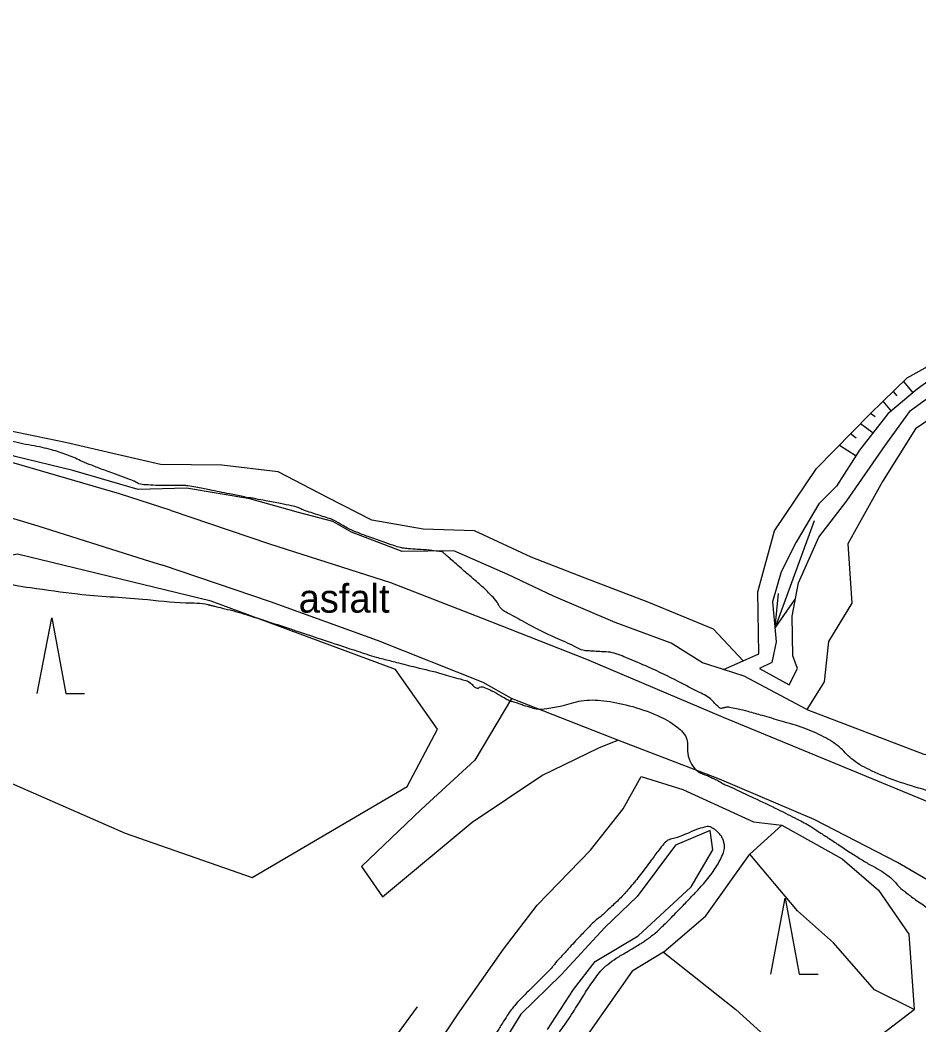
# Model space of a CAD drawing. Extents: x -475575 to -473225, y -1116053 to -1114104.
# Drawn here: x -473889.9 to -473842.5, y -1115632.7 to -1115579.7 of the extents above; entities that cross this region are included whole.
import ezdxf

# ---------------------------------------------------------------- set-up
doc = ezdxf.new("R2010")
doc.units = 0
doc.layers.add('Vrstevnice_vedlejsi', color=7, linetype='Continuous')
doc.layers.add('Vrstva_10', color=7, linetype='Continuous')

msp = doc.modelspace()

# ---------------------------------------------------------------- linework, layer by layer
at = {"layer": 'Vrstevnice_vedlejsi'}
for points in [[(-473898.863, -1115590.941), (-473898.35500000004, -1115588.119), (-473897.685, -1115585.314), (-473896.85400000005, -1115582.527), (-473895.863, -1115579.757), (-473895.07, -1115577.408), (-473894.47500000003, -1115575.479), (-473894.07800000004, -1115573.969), (-473893.923, -1115572.8050000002), (-473894.009, -1115571.985), (-473894.336, -1115571.51), (-473894.411, -1115569.968), (-473894.233, -1115567.357), (-473893.80100000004, -1115563.679), (-473892.655, -1115560.5990000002), (-473890.79500000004, -1115558.118), (-473888.22000000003, -1115556.237), (-473885.87600000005, -1115554.48), (-473883.76300000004, -1115552.85), (-473881.88200000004, -1115551.344), (-473877.041, -1115547.641), (-473869.242, -1115541.74), (-473858.483, -1115533.641), (-473850.92500000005, -1115528.022), (-473846.565, -1115524.882), (-473845.405, -1115524.2210000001), (-473843.21300000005, -1115523.172), (-473839.989, -1115521.735), (-473835.732, -1115519.909), (-473830.05100000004, -1115523.3490000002), (-473822.946, -1115532.0550000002), (-473814.417, -1115546.0280000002), (-473808.341, -1115555.6060000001), (-473804.71800000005, -1115560.789), (-473803.549, -1115561.578), (-473802.722, -1115562.1670000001), (-473802.237, -1115562.5550000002), (-473802.09300000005, -1115562.742), (-473802.14, -1115563.413), (-473802.379, -1115564.5690000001), (-473802.808, -1115566.21), (-473802.66500000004, -1115567.262), (-473801.95, -1115567.726), (-473800.662, -1115567.601), (-473799.61100000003, -1115567.898), (-473798.79500000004, -1115568.615), (-473798.21400000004, -1115569.753), (-473797.28400000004, -1115570.6700000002), (-473796.004, -1115571.365), (-473794.373, -1115571.8390000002), (-473792.50700000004, -1115572.905), (-473790.40400000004, -1115574.566), (-473788.06600000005, -1115576.82), (-473786.25200000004, -1115578.34), (-473784.96300000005, -1115579.1260000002), (-473784.199, -1115579.1770000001), (-473783.66500000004, -1115579.272), (-473783.36100000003, -1115579.408), (-473783.287, -1115579.587), (-473783.168, -1115579.7510000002), (-473783.00200000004, -1115579.9000000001), (-473782.791, -1115580.0350000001), (-473782.597, -1115580.119), (-473782.42100000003, -1115580.151), (-473782.26300000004, -1115580.1330000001), (-473782.069, -1115580.075), (-473781.83900000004, -1115579.9780000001), (-473781.574, -1115579.841), (-473781.348, -1115579.73), (-473781.161, -1115579.645), (-473781.015, -1115579.585), (-473780.88, -1115579.534), (-473780.755, -1115579.4910000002), (-473780.64200000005, -1115579.4570000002), (-473780.40900000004, -1115579.301), (-473780.058, -1115579.024), (-473779.587, -1115578.6260000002), (-473779.184, -1115578.3260000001), (-473778.847, -1115578.125), (-473778.57800000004, -1115578.022), (-473778.23600000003, -1115577.896), (-473777.819, -1115577.745), (-473777.329, -1115577.571), (-473776.63200000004, -1115577.3800000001), (-473775.728, -1115577.172), (-473774.617, -1115576.948), (-473773.862, -1115576.801), (-473773.465, -1115576.732), (-473773.424, -1115576.7410000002), (-473773.38200000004, -1115576.7510000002), (-473773.33800000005, -1115576.762), (-473773.294, -1115576.773), (-473772.905, -1115577.046), (-473772.17100000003, -1115577.5790000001), (-473771.09400000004, -1115578.374), (-473770.33900000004, -1115578.918), (-473769.906, -1115579.213)], [(-473855.174, -1115614.605), (-473856.74100000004, -1115613.852), (-473857.939, -1115613.34), (-473858.76900000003, -1115613.067), (-473859.23000000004, -1115613.0350000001), (-473859.60000000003, -1115613.011), (-473859.879, -1115612.997), (-473860.06600000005, -1115612.992), (-473860.656, -1115612.76), (-473861.65, -1115612.3020000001), (-473863.047, -1115611.617), (-473864.026, -1115611.075), (-473864.58900000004, -1115610.6770000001), (-473864.734, -1115610.421), (-473865.025, -1115610.081), (-473865.46300000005, -1115609.655), (-473866.048, -1115609.1430000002), (-473866.527, -1115608.7240000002), (-473866.902, -1115608.398), (-473867.172, -1115608.164), (-473867.375, -1115607.986), (-473867.511, -1115607.862), (-473867.579, -1115607.794), (-473867.842, -1115607.733), (-473868.299, -1115607.6800000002), (-473868.95, -1115607.635), (-473869.42500000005, -1115607.597), (-473869.723, -1115607.567), (-473869.84400000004, -1115607.543), (-473870.189, -1115607.435), (-473870.756, -1115607.24), (-473871.547, -1115606.9610000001), (-473872.174, -1115606.717), (-473872.64, -1115606.5080000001), (-473872.94200000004, -1115606.335), (-473873.16500000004, -1115606.208), (-473873.309, -1115606.1260000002), (-473873.373, -1115606.09), (-473873.586, -1115606.012), (-473873.94800000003, -1115605.891), (-473874.45800000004, -1115605.727), (-473874.84400000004, -1115605.5960000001), (-473875.10500000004, -1115605.497), (-473875.243, -1115605.4300000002), (-473875.59500000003, -1115605.3360000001), (-473876.162, -1115605.215), (-473876.945, -1115605.067), (-473877.478, -1115604.968), (-473877.76200000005, -1115604.9170000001), (-473877.797, -1115604.916), (-473878.167, -1115604.845), (-473878.87, -1115604.7040000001), (-473879.908, -1115604.494), (-473880.63800000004, -1115604.351), (-473881.059, -1115604.276), (-473881.172, -1115604.269), (-473881.492, -1115604.263), (-473882.02, -1115604.2580000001), (-473882.756, -1115604.2550000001), (-473883.299, -1115604.2240000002), (-473883.64900000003, -1115604.168), (-473883.80600000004, -1115604.085), (-473884.168, -1115603.936), (-473884.734, -1115603.7210000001), (-473885.504, -1115603.44), (-473886.13700000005, -1115603.1970000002), (-473886.631, -1115602.993), (-473886.988, -1115602.827), (-473887.36000000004, -1115602.675), (-473887.74600000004, -1115602.5350000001), (-473888.147, -1115602.409), (-473888.62, -1115602.289), (-473889.166, -1115602.174), (-473889.783, -1115602.065), (-473890.364, -1115601.922), (-473890.907, -1115601.747), (-473891.413, -1115601.538), (-473892.02, -1115601.304), (-473892.727, -1115601.0450000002), (-473893.536, -1115600.761), (-473894.18200000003, -1115600.5180000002), (-473894.667, -1115600.315), (-473894.99100000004, -1115600.151), (-473895.5, -1115599.8900000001), (-473896.194, -1115599.53), (-473897.075, -1115599.073), (-473897.715, -1115598.744), (-473898.114, -1115598.5450000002), (-473898.27300000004, -1115598.475), (-473898.558, -1115598.313), (-473898.96900000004, -1115598.058), (-473899.506, -1115597.71), (-473899.78900000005, -1115597.0790000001), (-473899.819, -1115596.163), (-473899.59500000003, -1115594.963), (-473899.277, -1115593.223), (-473898.863, -1115590.941)], [(-473918.52735009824, -1115615.8243041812), (-473918.527, -1115615.824), (-473916.922, -1115614.645), (-473915.13200000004, -1115613.726), (-473912.96900000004, -1115612.688), (-473910.433, -1115611.531), (-473907.525, -1115610.2550000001), (-473905.55600000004, -1115609.378), (-473904.526, -1115608.902), (-473904.435, -1115608.825), (-473904.368, -1115608.7680000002), (-473904.324, -1115608.729), (-473904.30500000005, -1115608.709), (-473903.532, -1115608.5080000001), (-473902.00700000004, -1115608.127), (-473899.72900000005, -1115607.566), (-473897.987, -1115607.267), (-473896.781, -1115607.2310000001), (-473896.112, -1115607.458), (-473895.516, -1115607.621), (-473894.992, -1115607.7210000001), (-473894.542, -1115607.756), (-473894.043, -1115607.842), (-473893.494, -1115607.9780000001), (-473892.897, -1115608.165), (-473892.27400000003, -1115608.441), (-473891.62600000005, -1115608.8050000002), (-473890.95300000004, -1115609.2580000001), (-473889.367, -1115609.652), (-473886.869, -1115609.986), (-473883.45900000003, -1115610.261), (-473881.17100000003, -1115610.448), (-473880.003, -1115610.547), (-473879.957, -1115610.5590000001), (-473879.91400000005, -1115610.57), (-473879.875, -1115610.58), (-473879.83800000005, -1115610.5890000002), (-473879.628, -1115610.639), (-473879.243, -1115610.733), (-473878.683, -1115610.868), (-473877.574, -1115611.205), (-473875.91400000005, -1115611.743), (-473873.70300000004, -1115612.483), (-473872.107, -1115613.009), (-473871.124, -1115613.321), (-473870.756, -1115613.419), (-473870.05500000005, -1115613.597), (-473869.021, -1115613.8560000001), (-473867.655, -1115614.196), (-473866.693, -1115614.476), (-473866.135, -1115614.696), (-473865.981, -1115614.8560000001), (-473865.841, -1115614.942), (-473865.716, -1115614.952)], [(-473787.44200000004, -1115614.95), (-473789.08300000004, -1115614.87), (-473790.19100000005, -1115614.817), (-473790.764, -1115614.7920000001), (-473790.802, -1115614.7950000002), (-473790.829, -1115614.797), (-473790.84300000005, -1115614.799), (-473790.846, -1115614.8020000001), (-473791.14200000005, -1115614.941), (-473791.734, -1115615.218), (-473792.619, -1115615.632), (-473793.44200000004, -1115615.992), (-473794.201, -1115616.298), (-473794.896, -1115616.55), (-473795.445, -1115616.8090000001), (-473795.847, -1115617.073), (-473796.103, -1115617.344), (-473796.93200000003, -1115617.5080000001), (-473798.336, -1115617.566), (-473800.313, -1115617.517), (-473801.81700000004, -1115617.777), (-473802.84900000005, -1115618.3460000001), (-473803.40900000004, -1115619.2240000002), (-473804.043, -1115619.781), (-473804.75200000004, -1115620.017), (-473805.53500000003, -1115619.932), (-473806.19, -1115619.8900000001), (-473806.71800000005, -1115619.8930000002), (-473807.117, -1115619.939), (-473807.568, -1115619.9610000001), (-473808.07, -1115619.959), (-473808.62200000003, -1115619.932), (-473809.50100000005, -1115620.717), (-473810.704, -1115622.313), (-473812.233, -1115624.72), (-473813.36000000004, -1115626.299), (-473814.08300000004, -1115627.051), (-473814.40400000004, -1115626.975), (-473815.069, -1115626.8730000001), (-473816.07800000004, -1115626.746), (-473817.43100000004, -1115626.593), (-473818.49100000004, -1115626.466), (-473819.25800000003, -1115626.365), (-473819.732, -1115626.291), (-473820.472, -1115626.1500000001), (-473821.476, -1115625.942), (-473822.745, -1115625.668), (-473823.906, -1115625.423), (-473824.95800000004, -1115625.2070000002), (-473825.902, -1115625.021), (-473826.77900000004, -1115624.814), (-473827.59, -1115624.5860000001), (-473828.335, -1115624.338), (-473829.00700000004, -1115624.1500000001), (-473829.608, -1115624.021), (-473830.136, -1115623.9510000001), (-473830.772, -1115623.8490000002), (-473831.515, -1115623.7140000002), (-473832.36600000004, -1115623.5450000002), (-473833.048, -1115623.359), (-473833.56200000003, -1115623.154), (-473833.90900000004, -1115622.9300000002), (-473834.20800000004, -1115622.723), (-473834.461, -1115622.531), (-473834.667, -1115622.3560000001), (-473835.119, -1115622.146), (-473835.81600000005, -1115621.902), (-473836.759, -1115621.6230000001), (-473837.57300000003, -1115621.401), (-473838.25800000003, -1115621.235), (-473838.815, -1115621.1260000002), (-473839.335, -1115621.0280000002), (-473839.818, -1115620.942), (-473840.26300000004, -1115620.8660000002), (-473841.082, -1115620.6500000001), (-473842.27400000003, -1115620.294), (-473843.83900000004, -1115619.797), (-473845.09400000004, -1115619.26), (-473846.03900000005, -1115618.682), (-473846.674, -1115618.064), (-473847.504, -1115617.527), (-473848.52900000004, -1115617.071), (-473849.749, -1115616.6970000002), (-473850.73500000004, -1115616.405), (-473851.488, -1115616.196), (-473852.00800000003, -1115616.0690000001), (-473852.386, -1115615.992), (-473852.62200000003, -1115615.9640000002), (-473852.715, -1115615.985), (-473852.79600000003, -1115616.004), (-473852.86500000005, -1115616.02), (-473852.922, -1115616.034), (-473853.03, -1115615.967), (-473853.189, -1115615.818), (-473853.39800000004, -1115615.587), (-473854.06, -1115615.183), (-473855.174, -1115614.605)], [(-473865.716, -1115614.952), (-473865.60400000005, -1115614.888), (-473865.37100000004, -1115614.935), (-473865.015, -1115615.095), (-473864.537, -1115615.3660000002), (-473864.20300000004, -1115615.55), (-473864.01200000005, -1115615.645), (-473863.965, -1115615.652), (-473863.87100000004, -1115615.679), (-473863.73000000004, -1115615.725), (-473863.542, -1115615.791), (-473863.303, -1115615.868), (-473863.014, -1115615.955), (-473862.67600000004, -1115616.0520000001), (-473862.109, -1115616.03), (-473861.315, -1115615.888), (-473860.294, -1115615.6260000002), (-473859.112, -1115615.625), (-473857.77, -1115615.884), (-473856.26800000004, -1115616.404), (-473855.25100000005, -1115616.996), (-473854.71900000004, -1115617.661), (-473854.672, -1115618.399), (-473854.476, -1115618.9640000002), (-473854.131, -1115619.3560000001), (-473853.63700000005, -1115619.5760000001), (-473853.26900000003, -1115619.7480000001), (-473853.025, -1115619.871), (-473852.907, -1115619.946), (-473852.79600000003, -1115620.0080000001), (-473852.69200000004, -1115620.057), (-473852.596, -1115620.092), (-473852.098, -1115620.3220000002), (-473851.19800000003, -1115620.749), (-473849.896, -1115621.37), (-473848.89, -1115621.8760000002), (-473848.179, -1115622.264), (-473847.764, -1115622.536), (-473847.28, -1115622.854), (-473846.728, -1115623.217), (-473846.108, -1115623.627), (-473845.536, -1115623.9880000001), (-473845.011, -1115624.299), (-473844.53500000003, -1115624.5620000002), (-473844.141, -1115624.825), (-473843.83, -1115625.09), (-473843.602, -1115625.3560000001), (-473843.23500000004, -1115625.682), (-473842.728, -1115626.0690000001), (-473842.08300000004, -1115626.5150000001), (-473841.466, -1115627.0010000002), (-473840.87700000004, -1115627.526), (-473840.31600000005, -1115628.092), (-473839.84900000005, -1115628.541), (-473839.47500000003, -1115628.875), (-473839.194, -1115629.094), (-473838.93700000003, -1115629.283), (-473838.704, -1115629.4440000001), (-473838.495, -1115629.574), (-473838.13200000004, -1115629.887), (-473837.61600000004, -1115630.381), (-473836.946, -1115631.057), (-473836.35400000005, -1115631.7550000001), (-473835.84, -1115632.475), (-473835.40300000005, -1115633.217), (-473835.03900000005, -1115633.7580000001), (-473834.748, -1115634.1), (-473834.52900000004, -1115634.242), (-473834.532, -1115634.763), (-473834.75800000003, -1115635.665), (-473835.206, -1115636.946), (-473835.64900000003, -1115637.798), (-473836.087, -1115638.22), (-473836.51800000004, -1115638.213), (-473836.874, -1115638.31), (-473837.152, -1115638.512), (-473837.35500000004, -1115638.82), (-473837.449, -1115639.148), (-473837.435, -1115639.496), (-473837.313, -1115639.865), (-473837.31, -1115640.549), (-473837.424, -1115641.548), (-473837.657, -1115642.861), (-473837.92600000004, -1115643.986), (-473838.232, -1115644.924), (-473838.576, -1115645.675), (-473838.944, -1115646.6030000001), (-473839.337, -1115647.708), (-473839.756, -1115648.99), (-473840.206, -1115650.12), (-473840.68600000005, -1115651.098), (-473841.196, -1115651.924), (-473842.265, -1115653.6870000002), (-473843.89300000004, -1115656.388), (-473846.08, -1115660.026), (-473847.81100000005, -1115663.024), (-473849.08800000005, -1115665.384)], [(-473861.82700000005, -1115633.554), (-473861.58300000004, -1115633.283), (-473861.319, -1115632.945), (-473861.03400000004, -1115632.54), (-473860.728, -1115632.066), (-473860.456, -1115631.638), (-473860.217, -1115631.257), (-473860.011, -1115630.9200000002), (-473859.782, -1115630.58), (-473859.532, -1115630.234), (-473859.259, -1115629.884), (-473858.89900000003, -1115629.5450000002), (-473858.451, -1115629.216), (-473857.91500000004, -1115628.898), (-473857.505, -1115628.6530000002), (-473857.21900000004, -1115628.4810000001), (-473857.058, -1115628.382), (-473856.86600000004, -1115628.25), (-473856.64400000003, -1115628.085), (-473856.39, -1115627.887), (-473856.01900000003, -1115627.546), (-473855.53, -1115627.061), (-473854.923, -1115626.433), (-473854.423, -1115625.911), (-473854.032, -1115625.495), (-473853.748, -1115625.185), (-473853.473, -1115624.834), (-473853.20900000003, -1115624.441), (-473852.954, -1115624.007), (-473852.794, -1115623.642), (-473852.73000000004, -1115623.347), (-473852.761, -1115623.121), (-473852.82700000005, -1115622.9170000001), (-473852.93100000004, -1115622.737), (-473853.07, -1115622.5790000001), (-473853.21400000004, -1115622.45), (-473853.363, -1115622.348), (-473853.51700000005, -1115622.2750000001), (-473853.798, -1115622.3), (-473854.206, -1115622.425), (-473854.742, -1115622.648), (-473855.15, -1115622.807), (-473855.43000000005, -1115622.902), (-473855.58400000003, -1115622.933), (-473855.721, -1115622.99), (-473855.84, -1115623.073), (-473855.943, -1115623.182), (-473856.199, -1115623.506), (-473856.608, -1115624.047), (-473857.17000000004, -1115624.803), (-473857.705, -1115625.46), (-473858.21300000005, -1115626.02), (-473858.694, -1115626.4810000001), (-473859.076, -1115626.8360000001), (-473859.36100000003, -1115627.0860000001), (-473859.547, -1115627.229), (-473859.879, -1115627.55), (-473860.356, -1115628.047), (-473860.98000000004, -1115628.7210000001), (-473861.433, -1115629.219), (-473861.715, -1115629.541), (-473861.82700000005, -1115629.688), (-473862.09300000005, -1115629.973), (-473862.51300000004, -1115630.395), (-473863.087, -1115630.956), (-473863.52400000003, -1115631.399), (-473863.824, -1115631.726), (-473863.988, -1115631.935), (-473864.2, -1115632.2410000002), (-473864.45900000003, -1115632.644), (-473864.766, -1115633.144), (-473865.031, -1115633.5450000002), (-473865.25200000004, -1115633.845), (-473865.43100000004, -1115634.046), (-473865.733, -1115634.413), (-473866.157, -1115634.9470000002), (-473866.705, -1115635.647), (-473867.152, -1115636.202), (-473867.5, -1115636.609), (-473867.748, -1115636.871), (-473868.237, -1115637.369), (-473868.967, -1115638.105), (-473869.938, -1115639.078), (-473870.68600000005, -1115639.8360000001), (-473871.212, -1115640.381), (-473871.515, -1115640.712), (-473871.776, -1115641.031), (-473871.994, -1115641.3390000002), (-473872.17000000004, -1115641.635), (-473872.347, -1115641.948), (-473872.52400000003, -1115642.276), (-473872.70300000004, -1115642.621), (-473872.886, -1115642.967), (-473873.074, -1115643.313), (-473873.266, -1115643.661), (-473873.527, -1115643.9810000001), (-473873.85500000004, -1115644.271)]]:
    msp.add_spline(points, degree=3, dxfattribs=at)
at = {"layer": 'Vrstva_10'}
for p, q in [((-473843.2905834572, -1115598.7767146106), (-473842.79158592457, -1115599.374360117)), ((-473844.3743094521, -1115599.8191610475), (-473843.94300808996, -1115600.3357273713)), ((-473843.8324464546, -1115599.2979378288), (-473843.64638667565, -1115599.520780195)), ((-473845.0229827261, -1115600.4431260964), (-473844.7884390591, -1115600.6240319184)), ((-473845.55107582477, -1115600.9829784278), (-473844.8946819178, -1115601.4892614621)), ((-473846.07810006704, -1115601.523655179), (-473845.78795615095, -1115601.7474460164)), ((-473846.66808205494, -1115602.1289205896), (-473845.78640174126, -1115602.6941839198)), ((-473848.0063875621, -1115606.119125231), (-473850.0544781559, -1115611.7587462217))]:
    msp.add_line(p, q, dxfattribs=at)
for points in [[(-473851.74700000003, -1115613.523), (-473853.321, -1115611.8460000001), (-473856.731, -1115610.4340000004), (-473860.085, -1115609.1570000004), (-473862.94100000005, -1115608.044), (-473865.927, -1115606.655), (-473868.64, -1115606.571), (-473871.34400000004, -1115606.0960000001), (-473873.69100000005, -1115604.899), (-473876.288, -1115603.5490000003), (-473879.27300000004, -1115603.1910000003), (-473882.51, -1115603.1540000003), (-473884.791, -1115602.631), (-473887.52, -1115601.9950000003), (-473890.58, -1115601.3530000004), (-473894.37, -1115600.129), (-473897.946, -1115598.4580000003), (-473901.11500000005, -1115596.8020000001), (-473904.707, -1115595.0220000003), (-473906.13800000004, -1115594.374)], [(-473881.9968808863, -1115605.55625309), (-473884.674, -1115604.6970000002), (-473890.76700000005, -1115602.9300000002), (-473894.433, -1115601.625), (-473898.283, -1115600.054), (-473902.07300000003, -1115598.486), (-473904.42600000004, -1115597.206), (-473906.375, -1115596.243), (-473908.146, -1115595.121)], [(-473912.217, -1115596.176), (-473909.196, -1115597.923), (-473905.22500000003, -1115599.787), (-473902.272, -1115601.304), (-473898.54000000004, -1115603.0390000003), (-473894.009, -1115604.871), (-473888.977, -1115606.3930000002), (-473883.37, -1115608.162), (-473882.3948296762, -1115608.463530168)], [(-473851.74700000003, -1115613.523), (-473850.92500000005, -1115613.1530000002), (-473850.967, -1115609.8700000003), (-473850.09300000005, -1115606.652), (-473847.87100000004, -1115603.3630000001), (-473845.053, -1115600.472), (-473843.08400000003, -1115598.578), (-473839.522, -1115596.5830000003)], [(-473852.794, -1115613.9734999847), (-473853.889, -1115613.6160000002), (-473855.55000000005, -1115612.58), (-473858.49700000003, -1115611.493), (-473861.756, -1115610.109), (-473864.16500000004, -1115608.96), (-473867.014, -1115607.719), (-473869.748, -1115607.7450000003), (-473872.42500000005, -1115606.733), (-473873.413, -1115606.168), (-473875.215, -1115605.692), (-473877.78400000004, -1115604.973), (-473881.129, -1115604.402), (-473883.684, -1115604.466), (-473887.135, -1115603.4640000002), (-473890.169, -1115602.7380000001), (-473894.28400000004, -1115601.286), (-473898.01300000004, -1115599.585), (-473901.579, -1115598.067), (-473904.53500000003, -1115596.72)], [(-473841.48500000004, -1115598.399), (-473842.56, -1115599.1810000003), (-473844.117, -1115600.4810000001), (-473845.601, -1115602.405), (-473846.814, -1115604.297), (-473847.754, -1115605.237), (-473848.95, -1115607.2450000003), (-473849.74100000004, -1115608.811), (-473850.19700000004, -1115610.408), (-473850.01200000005, -1115612.511), (-473850.244, -1115613.612), (-473850.879, -1115613.9200000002), (-473849.324, -1115614.783), (-473848.881, -1115613.925), (-473849.119, -1115613.2510000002), (-473849.16000000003, -1115611.1640000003), (-473848.826, -1115609.392), (-473847.75, -1115606.9950000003), (-473846.27400000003, -1115605.0760000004), (-473844.26200000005, -1115602.145), (-473842.91000000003, -1115600.3060000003), (-473841.32, -1115599.141)], [(-473840.44800000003, -1115599.78), (-473842.64400000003, -1115601.2650000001), (-473844.402, -1115604.047), (-473846.232, -1115607.3460000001), (-473846.00700000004, -1115610.4810000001), (-473847.237, -1115612.4980000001), (-473847.47500000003, -1115614.6200000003), (-473848.38700000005, -1115616.08)], [(-473881.9968808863, -1115605.55625309), (-473876.75200000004, -1115607.334), (-473870.36600000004, -1115609.379), (-473865.52900000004, -1115611.264), (-473860.025, -1115613.4240000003), (-473852.81200000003, -1115616.4950000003), (-473845.76900000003, -1115619.3970000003), (-473840.106, -1115621.73)], [(-473840.18000000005, -1115626.173), (-473843.61000000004, -1115624.169), (-473848.009, -1115621.889), (-473853.00100000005, -1115619.7550000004), (-473858.36000000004, -1115617.713), (-473863.98000000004, -1115615.504), (-473865.47500000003, -1115614.655), (-473871.048, -1115612.449), (-473876.706, -1115610.4030000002), (-473882.3948296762, -1115608.463530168)], [(-473849.02406476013, -1115610.2689971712), (-473850.0544781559, -1115611.7587462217), (-473849.88880664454, -1115609.9549566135)], [(-473889.00800000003, -1115615.247), (-473888.248, -1115611.247), (-473887.50800000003, -1115615.247), (-473886.50800000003, -1115615.247)], [(-473852.794, -1115613.9734999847), (-473851.74700000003, -1115613.523)], [(-473848.3870000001, -1115616.0799999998), (-473851.6990000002, -1115614.331), (-473852.79385247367, -1115613.9735481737)], [(-473863.98000000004, -1115615.504), (-473865.908, -1115618.7680000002), (-473868.75, -1115621.358), (-473871.90300000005, -1115624.3660000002), (-473870.79500000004, -1115625.973), (-473866.048, -1115622.034), (-473862.37700000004, -1115619.574), (-473859.36000000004, -1115618.1060000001), (-473858.36000000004, -1115617.713)], [(-473848.38700000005, -1115616.08), (-473842.20900000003, -1115618.452), (-473837.547, -1115619.243), (-473835.44700000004, -1115620.983)], [(-473868.575, -1115634.8330000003), (-473866.716, -1115632.053), (-473864.391, -1115628.739), (-473862.62600000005, -1115626.423), (-473859.80500000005, -1115623.516), (-473858.085, -1115621.3320000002), (-473857.13, -1115619.6300000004)], [(-473857.13, -1115619.6300000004), (-473854.927, -1115620.31), (-473851.21, -1115622.007), (-473849.715, -1115622.19)], [(-473862.076, -1115632.982), (-473860.711, -1115630.865), (-473859.55500000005, -1115629.3800000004), (-473857.283, -1115628.031), (-473854.495, -1115625.449), (-473853.34900000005, -1115623.496), (-473853.487, -1115622.479), (-473855.32800000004, -1115623.2480000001), (-473857.337, -1115625.948), (-473859.054, -1115627.5960000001), (-473861.363, -1115630.092), (-473863.489, -1115632.168), (-473864.64900000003, -1115634.0560000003)], [(-473855.95300000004, -1115628.9000000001), (-473853.727, -1115626.972), (-473851.397, -1115623.727), (-473849.715, -1115622.19)], [(-473849.715, -1115622.19), (-473846.51800000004, -1115623.9640000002), (-473844.601, -1115625.617), (-473842.99700000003, -1115627.939), (-473842.716, -1115631.915)], [(-473842.716, -1115631.915), (-473844.81200000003, -1115630.889), (-473846.98600000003, -1115628.402), (-473848.88, -1115626.7140000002), (-473851.397, -1115623.727)], [(-473850.292, -1115630.0520000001), (-473849.532, -1115626.0520000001), (-473848.792, -1115630.0520000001), (-473847.792, -1115630.0520000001)], [(-473855.95300000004, -1115628.9000000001), (-473857.613, -1115629.906), (-473859.836, -1115633.077), (-473862.06200000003, -1115635.698), (-473863.44200000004, -1115636.713), (-473865.56, -1115639.1130000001), (-473867.568, -1115640.666), (-473869.25800000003, -1115642.411), (-473870.036, -1115643.337), (-473871.326, -1115645.6800000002), (-473872.794, -1115647.057), (-473874.18000000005, -1115647.999), (-473876.101, -1115650.1800000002), (-473877.873, -1115652.298), (-473879, -1115653.771), (-473881.253, -1115656.5660000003), (-473884.18100000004, -1115658.9780000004), (-473885.494, -1115660.604), (-473887.598, -1115663.337), (-473889.063, -1115665.051), (-473891.26200000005, -1115667.348), (-473892.685, -1115669.671), (-473893.55000000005, -1115671.26), (-473894.332, -1115672.689)], [(-473855.95300000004, -1115628.9000000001), (-473852.134, -1115631.9240000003), (-473847.81700000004, -1115635.835), (-473842.716, -1115631.915)], [(-473868.9560000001, -1115631.7839999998), (-473875.7950000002, -1115641.126), (-473881.112, -1115647.6849999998)]]:
    msp.add_lwpolyline(points, dxfattribs=at)
msp.add_lwpolyline([(-473896.6254999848, -1115610.007), (-473898.19200000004, -1115613.561), (-473896.329, -1115616.327), (-473891.533, -1115619.48), (-473884.363, -1115622.608), (-473877.672, -1115624.948), (-473869.48749998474, -1115620.1500000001), (-473867.885, -1115617.129), (-473870.10400000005, -1115613.9740000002), (-473879.836, -1115610.369), (-473890.04500000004, -1115607.886), (-473894.118, -1115608.7280000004)], close=True, dxfattribs=at)

# ---------------------------------------------------------------- texts
msp.add_text('asfalt', height=1.5, dxfattribs=at).set_placement((-473875.2087404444, -1115610.9740878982))

doc.saveas('drawing.dxf')
